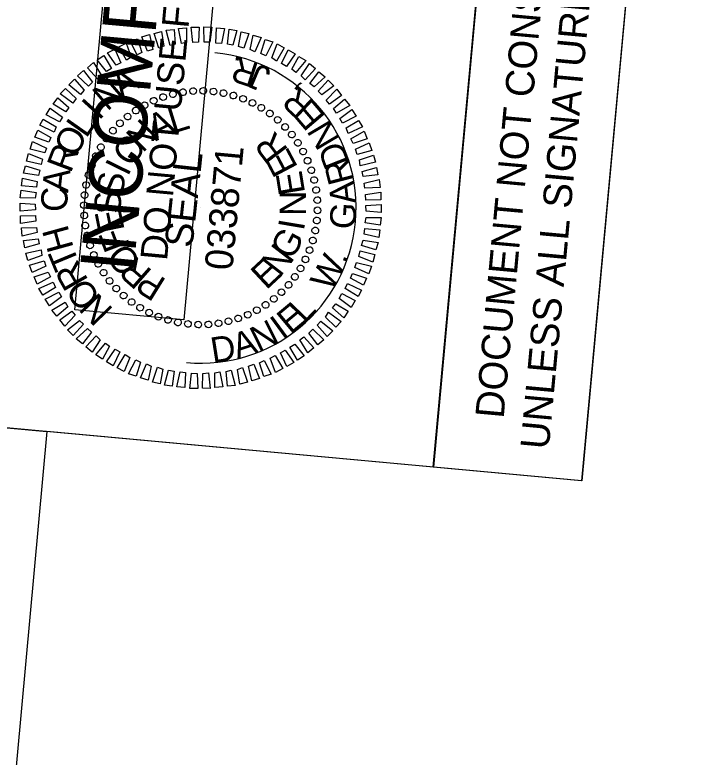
# Model space of a CAD drawing. Extents: x 2012234 to 2013485, y 445879 to 447846.
# Drawn here: x 2012453.8 to 2012600.1, y 447543.6 to 447702.9 of the extents above; entities that cross this region are included whole.
import ezdxf

# ---------------------------------------------------------------- set-up
doc = ezdxf.new("R2010")
doc.units = 0
for name, color, linetype in [('Old_Level_58', 7, 'Continuous'), ('Scratch_Level_0', 7, 'Continuous'), ('Sheet Clip Boundary CELL', 7, 'Continuous'), ('Sheet Plan And Profile CELL', 7, 'Continuous'), ('Sheet Professional Seal CELL', 7, 'Continuous'), ('Sheet Profile Grid Minor CELL', 7, 'Continuous'), ('Sheet Sticker Exception Certification CELL', 7, 'Continuous'), ('Sheet Sticker Incomplete CELL', 7, 'Continuous')]:
    doc.layers.add(name, color=color, linetype=linetype)

msp = doc.modelspace()

# ---------------------------------------------------------------- linework, layer by layer
at = {"layer": 'Old_Level_58'}
msp.add_lwpolyline([(2012375.92, 447420.36), (2012394.24, 447619.57), (2012460.65, 447613.46), (2012442.33, 447414.25)], close=True, dxfattribs=at)
at = {"layer": 'Scratch_Level_0'}
msp.add_arc((2012493.69, 447661.47), 33.36, 264.7467, 84.7467, dxfattribs=at)
at = {"layer": 'Sheet Clip Boundary CELL'}
msp.add_lwpolyline([(2012286.31, 446445.78), (2012511.43, 446429.21), (2012750.66, 446410.08), (2013333.05, 446362.08), (2013458.14, 447722.64), (2012593.82, 447802.11), (2012575.5, 447602.9), (2012460.65, 447613.46), (2012442.34, 447414.28), (2012375.93, 447420.39)], close=True, dxfattribs=at)
at = {"layer": 'Sheet Plan And Profile CELL'}
msp.add_lwpolyline([(2012431.63, 447616.13), (2012440.79, 447715.76), (2012552.82, 447705.46), (2012543.66, 447605.83)], close=True, dxfattribs=at)
at = {"layer": 'Sheet Professional Seal CELL'}
for p, q in [((2012494.24, 447686.58), (2012494.24, 447686.58)), ((2012485.64, 447685.26), (2012485.64, 447685.26)), ((2012487.7, 447685.87), (2012487.7, 447685.87)), ((2012489.85, 447686.28), (2012489.85, 447686.28)), ((2012492.07, 447686.47), (2012492.07, 447686.47)), ((2012496.44, 447686.42), (2012496.44, 447686.42)), ((2012498.62, 447686.07), (2012498.62, 447686.07)), ((2012500.72, 447685.53), (2012500.72, 447685.53)), ((2012481.61, 447683.47), (2012481.61, 447683.47)), ((2012483.6, 447684.44), (2012483.6, 447684.44)), ((2012502.77, 447684.89), (2012502.77, 447684.89)), ((2012504.8, 447684), (2012504.8, 447684)), ((2012479.75, 447682.38), (2012479.75, 447682.38)), ((2012506.71, 447682.92), (2012506.71, 447682.92)), ((2012477.97, 447681.04), (2012477.97, 447681.04)), ((2012508.56, 447681.74), (2012508.56, 447681.74)), ((2012510.24, 447680.33), (2012510.24, 447680.33)), ((2012476.33, 447679.64), (2012476.33, 447679.64)), ((2012511.86, 447678.83), (2012511.86, 447678.83)), ((2012474.83, 447678.02), (2012474.83, 447678.02)), ((2012513.26, 447677.19), (2012513.26, 447677.19)), ((2012473.42, 447676.34), (2012473.42, 447676.34)), ((2012514.61, 447675.41), (2012514.61, 447675.41)), ((2012472.24, 447674.49), (2012472.24, 447674.49)), ((2012471.16, 447672.58), (2012471.16, 447672.58)), ((2012515.69, 447673.56), (2012515.69, 447673.56)), ((2012516.66, 447671.56), (2012516.66, 447671.56)), ((2012470.28, 447670.55), (2012470.28, 447670.55)), ((2012517.48, 447669.53), (2012517.48, 447669.53)), ((2012469.63, 447668.5), (2012469.63, 447668.5)), ((2012518.09, 447667.46), (2012518.09, 447667.46)), ((2012469.09, 447666.39), (2012469.09, 447666.39)), ((2012518.5, 447665.32), (2012518.5, 447665.32)), ((2012468.74, 447664.22), (2012468.74, 447664.22)), ((2012518.7, 447663.09), (2012518.7, 447663.09)), ((2012468.59, 447662.02), (2012468.59, 447662.02)), ((2012493.69, 447661.47), (2012493.69, 447661.47)), ((2012468.69, 447659.85), (2012468.69, 447659.85)), ((2012518.8, 447660.92), (2012518.8, 447660.92)), ((2012518.65, 447658.72), (2012518.65, 447658.72)), ((2012468.89, 447657.63), (2012468.89, 447657.63)), ((2012518.29, 447656.55), (2012518.29, 447656.55)), ((2012469.29, 447655.48), (2012469.29, 447655.48)), ((2012469.9, 447653.41), (2012469.9, 447653.41)), ((2012517.75, 447654.44), (2012517.75, 447654.44)), ((2012517.11, 447652.39), (2012517.11, 447652.39)), ((2012470.72, 447651.38), (2012470.72, 447651.38)), ((2012516.22, 447650.36), (2012516.22, 447650.36)), ((2012471.69, 447649.38), (2012471.69, 447649.38)), ((2012515.14, 447648.45), (2012515.14, 447648.45)), ((2012472.78, 447647.53), (2012472.78, 447647.53)), ((2012474.12, 447645.75), (2012474.12, 447645.75)), ((2012513.97, 447646.6), (2012513.97, 447646.6)), ((2012475.53, 447644.11), (2012475.53, 447644.11)), ((2012512.56, 447644.92), (2012512.56, 447644.92)), ((2012477.15, 447642.61), (2012477.15, 447642.61)), ((2012511.05, 447643.3), (2012511.05, 447643.3)), ((2012478.82, 447641.2), (2012478.82, 447641.2)), ((2012507.64, 447640.56), (2012507.64, 447640.56)), ((2012509.42, 447641.9), (2012509.42, 447641.9)), ((2012480.67, 447640.02), (2012480.67, 447640.02)), ((2012482.58, 447638.94), (2012482.58, 447638.94)), ((2012505.78, 447639.47), (2012505.78, 447639.47)), ((2012484.61, 447638.05), (2012484.61, 447638.05)), ((2012486.66, 447637.41), (2012486.66, 447637.41)), ((2012501.75, 447637.68), (2012501.75, 447637.68)), ((2012503.78, 447638.5), (2012503.78, 447638.5)), ((2012488.77, 447636.87), (2012488.77, 447636.87)), ((2012490.95, 447636.52), (2012490.95, 447636.52)), ((2012493.14, 447636.37), (2012493.14, 447636.37)), ((2012495.31, 447636.47), (2012495.31, 447636.47)), ((2012497.54, 447636.66), (2012497.54, 447636.66)), ((2012499.68, 447637.07), (2012499.68, 447637.07))]:
    msp.add_line(p, q, dxfattribs=at)
for points in [[(2012487.16, 447696.32), (2012486.3, 447699.61), (2012487.97, 447699.75), (2012488.23, 447696.57)], [(2012489.6, 447696.69), (2012488.94, 447699.92), (2012490.66, 447700.06), (2012490.67, 447696.9)], [(2012492.03, 447696.92), (2012491.63, 447700.22), (2012493.34, 447700.22), (2012493.24, 447697.01)], [(2012494.45, 447697), (2012494.35, 447700.27), (2012496.05, 447700.22), (2012495.65, 447696.99)], [(2012496.94, 447696.82), (2012497.09, 447700.07), (2012498.78, 447699.92), (2012498.14, 447696.71)], [(2012499.43, 447696.54), (2012499.82, 447699.77), (2012501.46, 447699.52), (2012500.61, 447696.33)], [(2012480.04, 447694.26), (2012478.55, 447697.21), (2012480.15, 447697.71), (2012481.04, 447694.77)], [(2012482.27, 447695.06), (2012481.05, 447698.13), (2012482.7, 447698.63), (2012483.41, 447695.45)], [(2012484.69, 447695.74), (2012483.68, 447698.89), (2012485.27, 447699.3), (2012485.78, 447696.14)], [(2012501.79, 447696.07), (2012502.39, 447699.23), (2012504.06, 447698.88), (2012502.97, 447695.72)], [(2012504.3, 447695.44), (2012504.98, 447698.49), (2012506.64, 447697.99), (2012505.31, 447694.95)], [(2012477.73, 447693.17), (2012476.08, 447695.98), (2012477.66, 447696.79), (2012478.79, 447693.77)], [(2012506.63, 447694.58), (2012507.56, 447697.6), (2012509.17, 447697.1), (2012507.64, 447694.08)], [(2012508.95, 447693.61), (2012510.13, 447696.61), (2012511.61, 447695.82), (2012509.94, 447692.96)], [(2012475.57, 447692.06), (2012473.7, 447694.69), (2012475.23, 447695.5), (2012476.57, 447692.57)], [(2012511.05, 447692.41), (2012512.48, 447695.39), (2012513.95, 447694.5), (2012512.1, 447691.81)], [(2012473.49, 447690.74), (2012471.46, 447693.24), (2012472.9, 447694.16), (2012474.55, 447691.35)], [(2012513.25, 447691.2), (2012514.75, 447693.93), (2012516.23, 447693.04), (2012514.14, 447690.52)], [(2012471.53, 447689.17), (2012469.39, 447691.52), (2012470.7, 447692.61), (2012472.4, 447689.84)], [(2012515.28, 447689.81), (2012517.03, 447692.46), (2012518.33, 447691.34), (2012516.1, 447688.93)], [(2012469.63, 447687.53), (2012467.23, 447689.81), (2012468.53, 447690.9), (2012470.46, 447688.41)], [(2012517.13, 447688.14), (2012519.07, 447690.67), (2012520.43, 447689.59), (2012518.02, 447687.4)], [(2012467.91, 447685.78), (2012465.34, 447687.88), (2012466.56, 447689.07), (2012468.69, 447686.67)], [(2012518.89, 447686.47), (2012521.07, 447688.88), (2012522.26, 447687.66), (2012519.72, 447685.69)], [(2012466.23, 447683.88), (2012463.5, 447685.89), (2012464.67, 447687.09), (2012466.93, 447684.92)], [(2012520.62, 447684.55), (2012522.89, 447686.9), (2012523.92, 447685.55), (2012521.34, 447683.68)], [(2012464.71, 447682.06), (2012461.99, 447683.67), (2012462.98, 447685.08), (2012465.39, 447682.95)], [(2012522.21, 447682.75), (2012524.6, 447684.74), (2012525.69, 447683.43), (2012522.82, 447681.74)], [(2012463.35, 447679.88), (2012460.53, 447681.39), (2012461.37, 447682.87), (2012464, 447680.92)], [(2012523.57, 447680.62), (2012526.16, 447682.54), (2012527.08, 447681.1), (2012524.13, 447679.61)], [(2012462.2, 447677.72), (2012459.17, 447679.16), (2012459.89, 447680.5), (2012462.65, 447678.84)], [(2012524.89, 447678.59), (2012527.6, 447680.19), (2012528.43, 447678.81), (2012525.39, 447677.44)], [(2012461.1, 447675.56), (2012458.08, 447676.59), (2012458.72, 447678.09), (2012461.54, 447676.58)], [(2012525.93, 447676.28), (2012528.79, 447677.88), (2012529.45, 447676.26), (2012526.44, 447675.28)], [(2012460.23, 447673.23), (2012457.04, 447674.03), (2012457.59, 447675.69), (2012460.57, 447674.26)], [(2012526.93, 447674.03), (2012529.87, 447675.37), (2012530.42, 447673.76), (2012527.28, 447672.89)], [(2012459.45, 447670.74), (2012456.3, 447671.49), (2012456.7, 447673.11), (2012459.71, 447671.93)], [(2012527.78, 447671.74), (2012530.78, 447672.77), (2012531.24, 447671.22), (2012527.96, 447670.47)], [(2012458.83, 447668.39), (2012455.61, 447668.89), (2012456.06, 447670.5), (2012459.14, 447669.57)], [(2012528.35, 447669.23), (2012531.44, 447670.1), (2012531.75, 447668.52), (2012528.6, 447668.15)], [(2012458.45, 447665.92), (2012455.21, 447666.21), (2012455.42, 447667.85), (2012458.61, 447667.11)], [(2012528.78, 447666.78), (2012532.01, 447667.54), (2012532.2, 447665.81), (2012528.93, 447665.71)], [(2012458.18, 447663.53), (2012454.92, 447663.58), (2012455.12, 447665.22), (2012458.34, 447664.72)], [(2012529.1, 447664.34), (2012532.36, 447664.84), (2012532.36, 447663.19), (2012529.14, 447663.13)], [(2012458.2, 447661.02), (2012454.96, 447660.76), (2012454.92, 447662.47), (2012458.16, 447662.23)], [(2012529.18, 447661.92), (2012532.42, 447662.18), (2012532.46, 447660.47), (2012529.22, 447660.71)], [(2012458.28, 447658.6), (2012455.02, 447658.1), (2012455.02, 447659.75), (2012458.24, 447659.81)], [(2012529.2, 447659.41), (2012532.46, 447659.36), (2012532.26, 447657.72), (2012529.04, 447658.22)], [(2012458.61, 447656.16), (2012455.38, 447655.4), (2012455.18, 447657.13), (2012458.46, 447657.23)], [(2012528.93, 447657.03), (2012532.17, 447656.73), (2012531.97, 447655.09), (2012528.77, 447655.83)], [(2012459.04, 447653.71), (2012455.94, 447652.84), (2012455.64, 447654.43), (2012458.78, 447654.79)], [(2012528.55, 447654.55), (2012531.77, 447654.05), (2012531.32, 447652.44), (2012528.25, 447653.37)], [(2012459.61, 447651.2), (2012456.6, 447650.17), (2012456.14, 447651.72), (2012459.42, 447652.47)], [(2012527.94, 447652.2), (2012531.08, 447651.45), (2012530.68, 447649.83), (2012527.68, 447651.01)], [(2012460.45, 447648.91), (2012457.52, 447647.57), (2012456.96, 447649.18), (2012460.11, 447650.05)], [(2012527.16, 447649.71), (2012530.35, 447648.91), (2012529.79, 447647.26), (2012526.81, 447648.68)], [(2012461.45, 447646.66), (2012458.59, 447645.07), (2012457.94, 447646.68), (2012460.94, 447647.66)], [(2012526.29, 447647.38), (2012529.31, 447646.35), (2012528.67, 447644.85), (2012525.84, 447646.36)], [(2012462.49, 447644.35), (2012459.79, 447642.75), (2012458.96, 447644.13), (2012462, 447645.51)], [(2012525.19, 447645.22), (2012528.22, 447643.78), (2012527.49, 447642.45), (2012524.73, 447644.11)], [(2012463.81, 447642.33), (2012461.23, 447640.4), (2012460.31, 447641.84), (2012463.25, 447643.33)], [(2012524.03, 447643.06), (2012526.86, 447641.55), (2012526.02, 447640.07), (2012523.39, 447642.02)], [(2012465.17, 447640.19), (2012462.78, 447638.2), (2012461.7, 447639.51), (2012464.56, 447641.2)], [(2012522.68, 447640.88), (2012525.39, 447639.27), (2012524.41, 447637.86), (2012521.99, 447639.99)], [(2012466.77, 447638.39), (2012464.49, 447636.04), (2012463.46, 447637.39), (2012466.04, 447639.26)], [(2012521.16, 447639.06), (2012523.88, 447637.05), (2012522.72, 447635.86), (2012520.46, 447638.02)], [(2012468.5, 447636.47), (2012466.32, 447634.06), (2012465.12, 447635.28), (2012467.67, 447637.25)], [(2012519.47, 447637.16), (2012522.04, 447635.06), (2012520.83, 447633.87), (2012518.69, 447636.28)], [(2012470.25, 447634.8), (2012468.31, 447632.27), (2012466.96, 447633.35), (2012469.37, 447635.54)], [(2012472.11, 447633.13), (2012470.36, 447630.48), (2012469.05, 447631.6), (2012471.28, 447634.01)], [(2012517.76, 447635.41), (2012520.16, 447633.13), (2012518.85, 447632.04), (2012516.92, 447634.53)], [(2012474.14, 447631.74), (2012472.63, 447629.01), (2012471.16, 447629.9), (2012473.25, 447632.42)], [(2012515.85, 447633.78), (2012517.99, 447631.42), (2012516.69, 447630.33), (2012514.98, 447633.1)], [(2012476.34, 447630.53), (2012474.91, 447627.55), (2012473.43, 447628.44), (2012475.29, 447631.13)], [(2012511.82, 447630.88), (2012513.68, 447628.25), (2012512.15, 447627.44), (2012510.82, 447630.37)], [(2012513.9, 447632.2), (2012515.93, 447629.7), (2012514.49, 447628.78), (2012512.84, 447631.59)], [(2012478.44, 447629.33), (2012477.26, 447626.33), (2012475.77, 447627.12), (2012477.44, 447629.98)], [(2012509.66, 447629.78), (2012511.31, 447626.96), (2012509.73, 447626.15), (2012508.6, 447629.17)], [(2012480.76, 447628.37), (2012479.83, 447625.34), (2012478.21, 447625.84), (2012479.75, 447628.86)], [(2012483.09, 447627.5), (2012482.41, 447624.45), (2012480.74, 447624.95), (2012482.08, 447627.99)], [(2012505.11, 447627.88), (2012506.34, 447624.81), (2012504.69, 447624.31), (2012503.97, 447627.49)], [(2012507.35, 447628.68), (2012508.83, 447625.73), (2012507.23, 447625.23), (2012506.35, 447628.17)], [(2012485.59, 447626.87), (2012485, 447623.71), (2012483.32, 447624.06), (2012484.42, 447627.23)], [(2012487.96, 447626.4), (2012487.56, 447623.17), (2012485.93, 447623.42), (2012486.77, 447626.61)], [(2012490.44, 447626.12), (2012490.29, 447622.87), (2012488.6, 447623.03), (2012489.25, 447626.23)], [(2012497.78, 447626.25), (2012498.44, 447623.02), (2012496.72, 447622.88), (2012496.71, 447626.05)], [(2012500.23, 447626.63), (2012501.08, 447623.33), (2012499.41, 447623.19), (2012499.15, 447626.37)], [(2012502.69, 447627.2), (2012503.71, 447624.05), (2012502.11, 447623.64), (2012501.6, 447626.8)], [(2012492.94, 447625.94), (2012493.04, 447622.67), (2012491.33, 447622.72), (2012491.73, 447625.95)], [(2012495.35, 447626.02), (2012495.75, 447622.72), (2012494.05, 447622.73), (2012494.14, 447625.93)]]:
    msp.add_lwpolyline(points, close=True, dxfattribs=at)
for centre, major_axis in [((2012487.73, 447685.83), (-0.171, 0.699)), ((2012489.88, 447686.26), (-0.109, 0.712)), ((2012492.05, 447686.5), (-0.047, 0.718)), ((2012494.24, 447686.54), (0.016, 0.72)), ((2012496.42, 447686.4), (0.078, 0.716)), ((2012498.59, 447686.07), (0.141, 0.706)), ((2012483.59, 447684.43), (-0.29, 0.659)), ((2012485.63, 447685.22), (-0.231, 0.682)), ((2012500.71, 447685.55), (0.202, 0.691)), ((2012502.78, 447684.84), (0.261, 0.671)), ((2012481.63, 447683.46), (-0.346, 0.631)), ((2012504.79, 447683.96), (0.318, 0.646)), ((2012506.7, 447682.91), (0.374, 0.616)), ((2012478, 447681.03), (-0.451, 0.562)), ((2012479.76, 447682.32), (-0.4, 0.599)), ((2012508.52, 447681.7), (0.426, 0.581)), ((2012476.35, 447679.59), (-0.498, 0.52)), ((2012510.23, 447680.33), (0.475, 0.541)), ((2012474.84, 447678.01), (-0.541, 0.475)), ((2012511.81, 447678.81), (0.52, 0.498)), ((2012473.47, 447676.3), (-0.581, 0.426)), ((2012513.25, 447677.17), (0.562, 0.451)), ((2012514.55, 447675.4), (0.599, 0.4)), ((2012472.25, 447674.48), (-0.616, 0.374)), ((2012515.68, 447673.53), (0.631, 0.346)), ((2012471.2, 447672.56), (-0.646, 0.318)), ((2012516.65, 447671.57), (0.659, 0.29)), ((2012470.32, 447670.56), (-0.671, 0.261)), ((2012469.61, 447668.49), (-0.691, 0.202)), ((2012517.44, 447669.53), (0.682, 0.231)), ((2012518.05, 447667.43), (0.699, 0.171)), ((2012469.09, 447666.36), (-0.706, 0.141)), ((2012518.48, 447665.28), (0.712, 0.109)), ((2012468.76, 447664.2), (-0.716, 0.078)), ((2012468.62, 447662.02), (-0.72, 0.016)), ((2012518.72, 447663.11), (0.718, 0.047)), ((2012518.77, 447660.92), (0.72, -0.016)), ((2012468.67, 447659.83), (-0.718, -0.047)), ((2012518.62, 447658.74), (0.716, -0.078)), ((2012468.9, 447657.66), (-0.712, -0.109)), ((2012469.33, 447655.51), (-0.699, -0.171)), ((2012518.29, 447656.58), (0.706, -0.141)), ((2012517.77, 447654.45), (0.691, -0.202)), ((2012469.94, 447653.41), (-0.682, -0.231)), ((2012517.07, 447652.38), (0.671, -0.261)), ((2012470.74, 447651.37), (-0.659, -0.29)), ((2012471.7, 447649.41), (-0.631, -0.346)), ((2012516.19, 447650.38), (0.646, -0.318)), ((2012472.84, 447647.54), (-0.599, -0.4)), ((2012515.13, 447648.46), (0.616, -0.374)), ((2012513.92, 447646.64), (0.581, -0.426)), ((2012474.13, 447645.77), (-0.562, -0.451)), ((2012512.55, 447644.93), (0.541, -0.475)), ((2012475.57, 447644.13), (-0.52, -0.498)), ((2012511.03, 447643.35), (0.498, -0.52)), ((2012477.15, 447642.62), (-0.475, -0.541)), ((2012478.86, 447641.25), (-0.426, -0.581)), ((2012509.39, 447641.91), (0.451, -0.562)), ((2012480.68, 447640.03), (-0.374, -0.616)), ((2012507.62, 447640.62), (0.4, -0.599)), ((2012482.6, 447638.98), (-0.318, -0.646)), ((2012484.6, 447638.1), (-0.261, -0.671)), ((2012503.79, 447638.51), (0.29, -0.659)), ((2012505.75, 447639.48), (0.346, -0.631)), ((2012486.67, 447637.39), (-0.202, -0.691)), ((2012488.8, 447636.87), (-0.141, -0.706)), ((2012490.96, 447636.54), (-0.078, -0.716)), ((2012495.33, 447636.44), (0.047, -0.718)), ((2012497.51, 447636.68), (0.109, -0.712)), ((2012499.65, 447637.11), (0.171, -0.699)), ((2012501.75, 447637.72), (0.231, -0.682)), ((2012493.14, 447636.4), (-0.016, -0.72))]:
    msp.add_ellipse(centre, major_axis=major_axis, ratio=0.999708, dxfattribs=at)
at = {"layer": 'Sheet Sticker Exception Certification CELL'}
for p, q in [((2012543.64, 447605.83), (2012561.96, 447805.04)), ((2012593.8, 447802.11), (2012575.49, 447602.9)), ((2012575.49, 447602.9), (2012543.64, 447605.83))]:
    msp.add_line(p, q, dxfattribs=at)
at = {"layer": 'Sheet Sticker Incomplete CELL'}
msp.add_lwpolyline([(2012490.08, 447637.42), (2012466.67, 447639.57), (2012480.13, 447785.95), (2012503.53, 447783.8)], close=True, dxfattribs=at)

# ---------------------------------------------------------------- texts
at = {"layer": 'Sheet Professional Seal CELL'}
for s, height, rotation, p in [('A', 5.64, 33.3638, (2012476.8, 447684.71)), ('N', 5.64, 40.5656, (2012473.59, 447682.05)), ('I', 5.64, 47.7668, (2012471.85, 447680.05)), ('A', 5.64, 26.5069, (2012484.06, 447675.71)), ('L', 5.64, 17.1475, (2012487.67, 447677.34)), ('L', 5.64, 54.9675, (2012469.09, 447676.23)), ('N', 5.64, 45.2233, (2012481.21, 447673.11)), ('O', 5.64, 62.1678, (2012466.85, 447672.02)), ('R', 5.64, 127.2281, (2012512.66, 447673.89)), ('O', 5.64, 54.5801, (2012478.91, 447669.96)), ('R', 5.64, 69.3678, (2012465.79, 447668.76)), ('E', 5.64, 117.8707, (2012514.67, 447670.14)), ('SEAL', 5.998, 83.7467, (2012491.89, 447652.75)), ('I', 5.64, 63.9363, (2012478.03, 447668.03)), ('A', 5.64, 83.767, (2012465.21, 447664.59)), ('E', 5.64, 99.1584, (2012516.13, 447664.68)), ('S', 5.64, 82.6471, (2012476.94, 447663.81)), ('C', 5.64, 90.9665, (2012465.15, 447660.63)), ('S', 5.64, 92.0023, (2012476.66, 447660.22)), ('N', 5.64, 89.803, (2012516.27, 447659.7)), ('E', 5.64, 101.3577, (2012477.39, 447656.69)), ('I', 5.64, 80.4479, (2012515.82, 447656.37)), ('H', 5.64, 105.3661, (2012466.44, 447652.88)), ('F', 5.64, 110.7137, (2012478.59, 447653.37)), ('G', 5.64, 61.7369, (2012513.33, 447650.02)), ('O', 5.64, 129.4279, (2012481.22, 447649.81)), ('N', 5.64, 52.3806, (2012510.74, 447646.45)), ('T', 5.64, 112.5664, (2012467.79, 447649.49)), ('R', 5.64, 119.7672, (2012469.67, 447645.9)), ('R', 5.64, 138.7863, (2012483.5, 447647.85)), ('E', 5.64, 43.0235, (2012507.77, 447643.71)), ('O', 5.64, 126.9684, (2012472.44, 447642.19)), ('P', 5.64, 148.1455, (2012486.54, 447645.96)), ('N', 5.64, 134.1702, (2012475.11, 447639.63))]:
    msp.add_text(s, height=height, rotation=rotation, dxfattribs=at).set_placement(p)
at = {"layer": 'Sheet Profile Grid Minor CELL'}
for s, height, rotation, p in [('R', 5.5, 162.1007, (2012506.48, 447692.4)), ('.', 5.5, 169.0272, (2012502.66, 447693.72)), ('J', 5.5, 157.2322, (2012509.06, 447691.2)), (',', 5.5, 144.0519, (2012515.43, 447686.92)), ('R', 5.5, 137.1254, (2012518.34, 447684.11)), ('E', 5.5, 130.5425, (2012520.78, 447681.13)), ('N', 5.5, 120.6107, (2012523.76, 447676.17)), ('033871', 5.998, 84.7467, (2012500.49, 447647.89)), ('D', 5.5, 111.4661, (2012525.72, 447671.2)), ('R', 5.5, 104.5397, (2012526.66, 447667.27)), ('A', 5.5, 96.3539, (2012527.15, 447662.52)), ('G', 5.5, 86.4222, (2012526.82, 447656.73)), ('W', 5.5, 61.6358, (2012521.79, 447643.28)), ('.', 5.5, 73.2419, (2012524.87, 447649.3)), ('E', 5.5, 39.7975, (2012513, 447634.13)), ('L', 5.5, 46.3805, (2012516.01, 447636.53)), ('N', 5.5, 26.3453, (2012506.11, 447630.39)), ('I', 5.5, 36.277, (2012511.29, 447633)), ('D', 5.5, 9.0149, (2012496.29, 447628.1)), ('A', 5.5, 18.1595, (2012501.56, 447628.94))]:
    msp.add_text(s, height=height, rotation=rotation, dxfattribs=at).set_placement(p)
at = {"layer": 'Sheet Sticker Exception Certification CELL'}
for s, p in [('UNLESS ALL SIGNATURES COMPLETED', (2012568.42, 447609.47)), ('DOCUMENT NOT CONSIDERED FINAL', (2012558.73, 447616.12))]:
    msp.add_text(s, height=6.124, rotation=84.7467, dxfattribs=at).set_placement(p)
at = {"layer": 'Sheet Sticker Incomplete CELL'}
for s, height, p in [('INCOMPLETE PLANS', 11.52, (2012479.24, 447647.4)), ('DO NOT USE FOR R/W ACQUISITION', 5.76, (2012486.46, 447650))]:
    msp.add_text(s, height=height, rotation=84.7467, dxfattribs=at).set_placement(p)

doc.saveas('drawing.dxf')
